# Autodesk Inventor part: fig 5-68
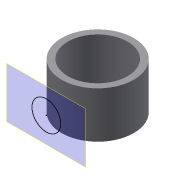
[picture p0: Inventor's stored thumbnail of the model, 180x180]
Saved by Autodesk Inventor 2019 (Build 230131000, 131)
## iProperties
Shininess: 64.0
Length Units: 11269
Angle Units: 11279
Time Units: 11290
Mass Units: 11283
Length Display Precision: 3
Angle Display Precision: 2
Compacted: True
Part Number: fig 5-68
Document SubType Name: Modeling
Created: 2002-12
Designer: deepak
Density: 1 g/cm^3
Material: Generic
Appearance: Default
Density: 0.0
Volumn: 0.0
Area: 0.0
PropertySet Name: Model Information
Control State: 0
Master: False
Checked Out: False
Author: deepak
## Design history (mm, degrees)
sketch "Sketch1"
  geometry: C1 r 23.454 at (0, 0); C2 r 19.43 at (0, 0)
  constraints: 2 centre point, 1 coincident, 1 concentric
extrude "Extrusion1" new body sketch "Sketch1" stored distance "d0" = 30; taper "d1" = 0 deg
workplane "Work Plane1"
workplane "Work Plane2"
sketch "Sketch2"
  geometry: C1 r 9.343 at (0, 0)
  constraints: 1 centre point
body "Solid1"
